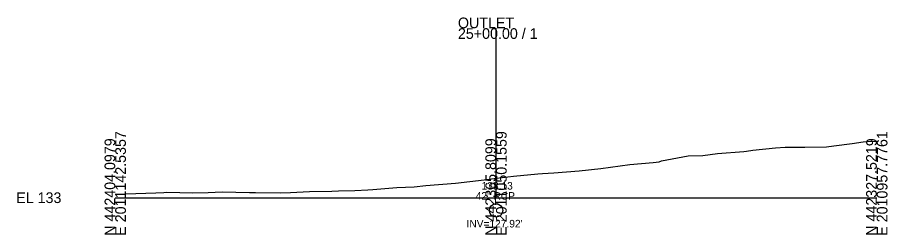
# Model space of a CAD drawing. Extents: x -26 to 1203, y -15 to 9526.
# Drawn here: x 974.3 to 1202.8, y 4990.3 to 5047.4 of the extents above; entities that cross this region are included whole.
import ezdxf

# ---------------------------------------------------------------- set-up
doc = ezdxf.new("R2010")
doc.units = 0
for name, color, linetype in [('Exist Cross Section Cell', 7, 'Continuous'), ('Exist XS Center Line Elevation Label', 7, 'Continuous'), ('Exist XS Ground Line', 7, 'Continuous'), ('Prop XSC Text', 7, 'Continuous')]:
    doc.layers.add(name, color=color, linetype=linetype)

msp = doc.modelspace()

# ---------------------------------------------------------------- linework, layer by layer
at = {"layer": 'Exist Cross Section Cell'}
for p, q in [((1100, 5000), (1100, 5044.53)), ((1000, 5000), (1100, 5000)), ((1100, 5000), (1200, 5000))]:
    msp.add_line(p, q, dxfattribs=at)
at = {"layer": 'Exist XS Ground Line'}
msp.add_lwpolyline([(1000, 5000.92), (1002.74, 5001.05), (1010.7, 5001.3), (1012.73, 5001.39), (1013.57, 5001.42), (1020.38, 5001.32), (1024.39, 5001.4), (1028.04, 5001.54), (1035.22, 5001.36), (1035.69, 5001.36), (1036.82, 5001.38), (1043.34, 5001.31), (1046.04, 5001.38), (1050.99, 5001.59), (1056.87, 5001.71), (1058.65, 5001.81), (1062.94, 5001.92), (1066.3, 5002.05), (1067.69, 5002.19), (1073.95, 5002.65), (1078.52, 5002.86), (1081.61, 5003.22), (1089.34, 5003.8), (1096.91, 5004.73), (1100.17, 5005.15), (1104.57, 5005.68), (1110.99, 5006.26), (1112.22, 5006.35), (1115.17, 5006.55), (1121.82, 5007.04), (1127.52, 5007.69), (1132.64, 5008.38), (1135.18, 5008.7), (1141.29, 5009.28), (1142.83, 5009.46), (1143.47, 5009.69), (1150.48, 5011.02), (1154.29, 5011.07), (1158.14, 5011.63), (1165.12, 5012.18), (1165.79, 5012.26), (1167.41, 5012.45), (1173.44, 5013.09), (1175.94, 5013.3), (1181.1, 5013.32), (1186.77, 5013.41), (1188.75, 5013.63), (1193.53, 5014.28), (1196.4, 5014.65), (1197.59, 5014.78), (1200, 5014.84)], dxfattribs=at)
at = {"layer": 'Prop XSC Text'}
msp.add_circle((1100, 4996.67), 1.75, dxfattribs=at)

# ---------------------------------------------------------------- texts
at = {"layer": 'Exist Cross Section Cell'}
for s, p in [('OUTLET', (1090, 5044.53)), ('25+00.00 / 1', (1090, 5041.73)), ('EL 133', (974, 4998.6))]:
    msp.add_text(s, height=2.8, dxfattribs=at).set_placement(p)
for s, p in [('E 2011142.5357', (1002.8, 4990)), ('E 2011050.1559', (1102.8, 4990)), ('E 2010957.7761', (1202.8, 4990)), ('N 442404.0979', (1000, 4990)), ('N 442365.8099', (1100, 4990)), ('N 442327.5219', (1200, 4990))]:
    msp.add_text(s, height=2.8, rotation=90, dxfattribs=at).set_placement(p)
at = {"layer": 'Exist XS Center Line Elevation Label'}
msp.add_text('138.13', height=2, dxfattribs=at).set_placement((1096.23, 5002.13))
at = {"layer": 'Prop XSC Text'}
for s, p in [('42" RCP', (1094.67, 4999.47)), ("INV=127.92'", (1092.26, 4992.18))]:
    msp.add_text(s, height=2, dxfattribs=at).set_placement(p)

doc.saveas('drawing.dxf')
